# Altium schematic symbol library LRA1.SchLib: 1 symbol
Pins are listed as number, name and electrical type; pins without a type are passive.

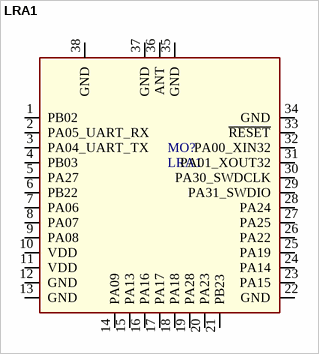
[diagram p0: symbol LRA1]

## LRA1
designator MO?
LoRa Module; Manufacturer: i2electronics
footprint LRA1
pins: 1 PB02, 2 PA05_UART_RX, 3 PA04_UART_TX, 4 PB03, 5 PA27, 6 PB22, 7 PA06, 8 PA07, 9 PA08, 10 VDD, 11 VDD, 12 GND, 13 GND, 14 PA09, 15 PA13, 16 PA16, 17 PA17, 18 PA18, 19 PA28, 20 PA23, 21 PB23, 22 GND, 23 PA15, 24 PA14, 25 PA19, 26 PA22, 27 PA25, 28 PA24, 29 PA31_SWDIO, 30 PA30_SWDCLK, 31 PA01_XOUT32, 32 PA00_XIN32, 33 ~{RESET}, 34 GND, 35 GND, 36 ANT, 37 GND, 38 GND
